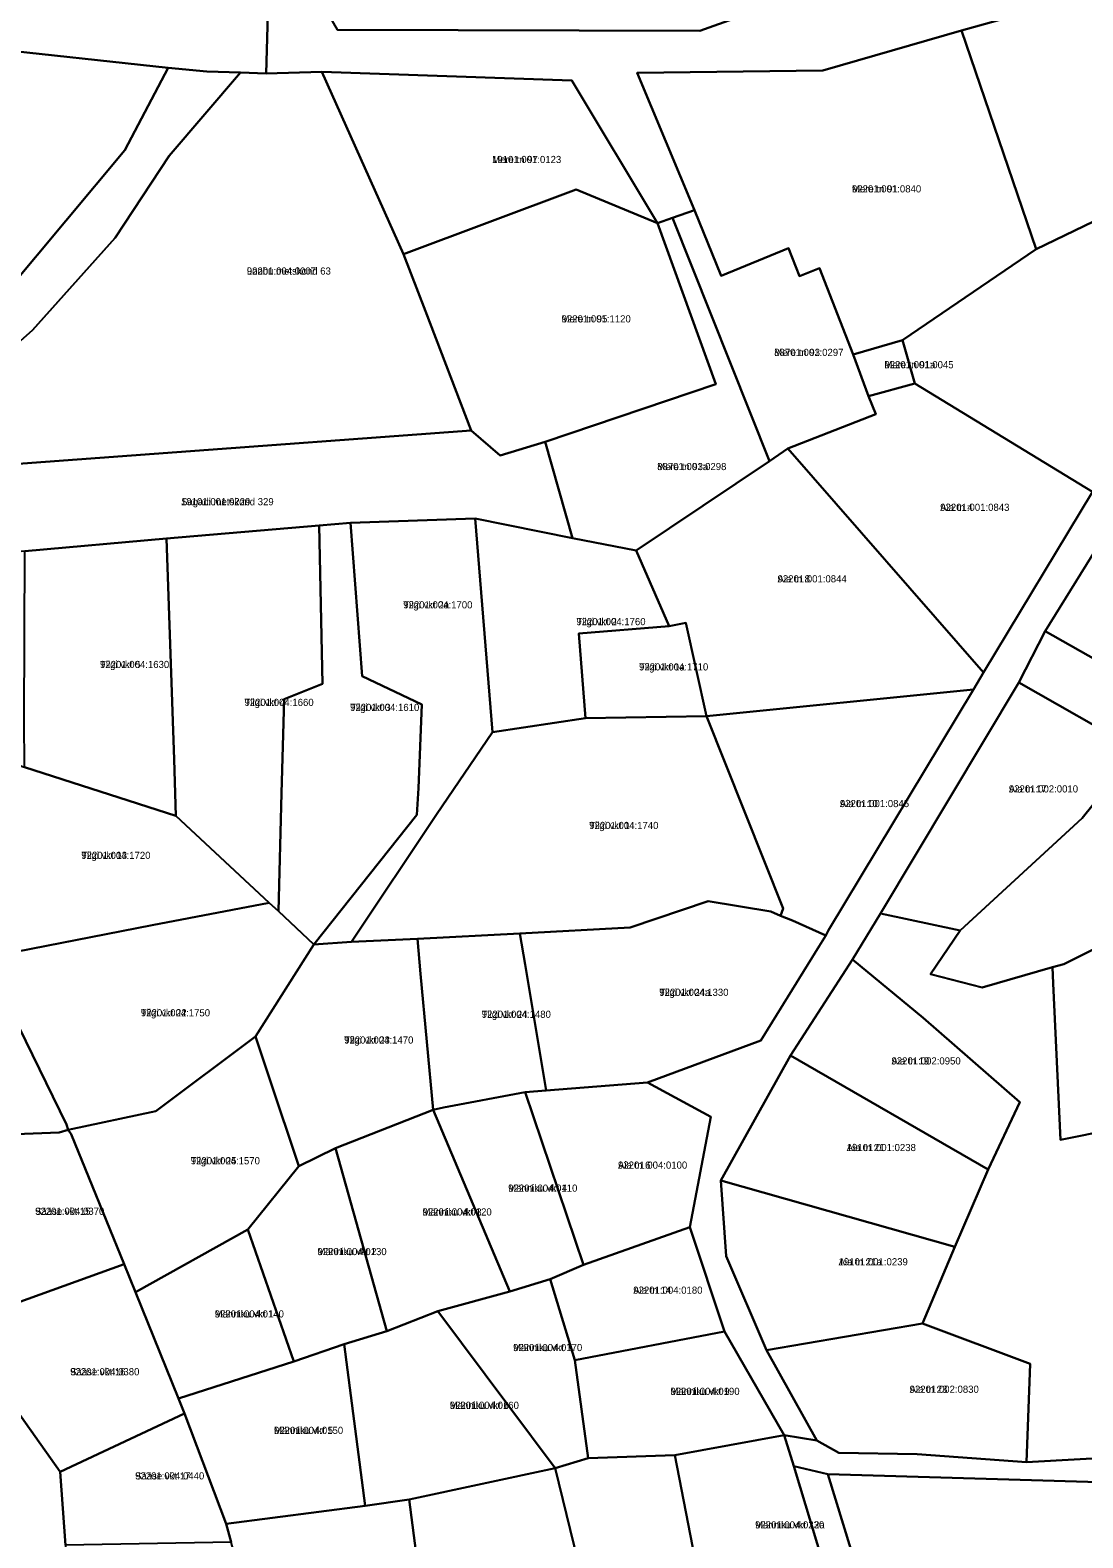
# Model space of a CAD drawing. Extents: x 601493 to 643081, y 6584980 to 6634019.
# Drawn here: x 610205.1 to 610425.7, y 6605427.7 to 6605743.8 of the extents above; entities that cross this region are included whole.
import ezdxf

# ---------------------------------------------------------------- set-up
doc = ezdxf.new("R2010")
doc.units = 0
for name, color, linetype in [('L_AADRESS', 7, 'Continuous'), ('PIIR', 7, 'Continuous'), ('TUNNUS', 7, 'Continuous')]:
    doc.layers.add(name, color=color, linetype=linetype)

msp = doc.modelspace()

# ---------------------------------------------------------------- linework, layer by layer
at = {"layer": 'PIIR'}
for points in [[(610289.98, 6605877.37), (610312.22, 6605837.37), (610292.43, 6605827.49), (610306.7, 6605795.06), (610329.91, 6605805.68), (610361.45, 6605749.4), (610345.37, 6605743.67), (610269.45, 6605743.86), (610216.52, 6605835.66)], [(610234, 6605735.88), (610224.92, 6605718.63), (610200.13, 6605689.04), (610179.93, 6605671.33), (610152.8, 6605650.08), (610007.23, 6605642.89), (609916.86, 6605639.32), (609908.54, 6605793.58), (609940.79, 6605777.71), (609965.38, 6605768.93), (609991.64, 6605761.28), (610037.32, 6605756.23), (610195.26, 6605740.09)], [(610400.23, 6605743.76), (610447.51, 6605756.94), (610456.9, 6605730.33), (610478.03, 6605737.44), (610478.38, 6605733.58), (610465.58, 6605711.74), (610456.1, 6605717.35), (610415.85, 6605697.91)], [(610370.48, 6605693.9), (610366.27, 6605692.21), (610364, 6605698.11), (610349.85, 6605692.34), (610344.31, 6605706.1), (610332.26, 6605734.83), (610371.17, 6605735.37), (610400.23, 6605743.76), (610415.85, 6605697.91), (610387.89, 6605678.79), (610377.56, 6605675.82)], [(610254.53, 6605734.73), (610266.17, 6605735.06), (610283.31, 6605696.84), (610287.89, 6605684.93), (610297.5, 6605659.86), (610164.51, 6605650.07), (610189.72, 6605666.95), (610205.55, 6605680.91), (610222.84, 6605700.29), (610234.19, 6605717.47), (610249.14, 6605734.93)], [(610266.17, 6605735.06), (610318.55, 6605733.23), (610336.54, 6605703.34), (610319.49, 6605710.43), (610283.31, 6605696.84)], [(610387.89, 6605678.79), (610415.85, 6605697.91), (610456.1, 6605717.35), (610465.58, 6605711.74), (610427.67, 6605647.04), (610390.42, 6605669.77)], [(610287.89, 6605684.93), (610283.31, 6605696.84), (610319.49, 6605710.43), (610336.54, 6605703.34), (610348.72, 6605669.59), (610312.97, 6605657.53), (610303.57, 6605654.66), (610297.5, 6605659.86)], [(610359.96, 6605653.45), (610339.7, 6605704.44), (610344.31, 6605706.1), (610349.85, 6605692.34), (610364, 6605698.11), (610366.27, 6605692.21), (610370.48, 6605693.9), (610377.56, 6605675.82), (610380.71, 6605667.07), (610382.27, 6605663.31), (610363.87, 6605656.09)], [(610348.72, 6605669.59), (610336.54, 6605703.34), (610339.7, 6605704.44), (610359.96, 6605653.45), (610332.06, 6605634.76), (610318.71, 6605637.3), (610312.97, 6605657.53)], [(610377.56, 6605675.82), (610387.89, 6605678.79), (610390.42, 6605669.77), (610380.71, 6605667.07)], [(610382.27, 6605663.31), (610380.71, 6605667.07), (610390.42, 6605669.77), (610427.67, 6605647.04), (610404.86, 6605609.15), (610363.87, 6605656.09)], [(610164.51, 6605650.07), (610297.5, 6605659.86), (610303.57, 6605654.66), (610312.97, 6605657.53), (610318.71, 6605637.3), (610298.29, 6605641.47), (610272.21, 6605640.5), (610265.64, 6605639.99), (610233.6, 6605637.22), (610203.92, 6605634.6), (610164.97, 6605631.15), (610135.51, 6605628.57)], [(610342.44, 6605619.56), (610339, 6605618.89), (610332.06, 6605634.76), (610359.96, 6605653.45), (610363.87, 6605656.09), (610404.86, 6605609.15), (610402.72, 6605605.58), (610346.79, 6605600)], [(610235.26, 6605590.9), (610233.6, 6605637.22), (610265.64, 6605639.99), (610266.32, 6605606.76), (610258.27, 6605603.57), (610257.74, 6605583.88), (610257.1, 6605559.12), (610255.11, 6605560.84), (610235.6, 6605579.07)], [(610257.1, 6605559.12), (610257.74, 6605583.88), (610258.27, 6605603.57), (610266.32, 6605606.76), (610265.64, 6605639.99), (610272.21, 6605640.5), (610274.6, 6605608.39), (610287.1, 6605602.44), (610286.44, 6605584.9), (610286.11, 6605579.31), (610264.52, 6605552.15)], [(610264.52, 6605552.15), (610286.11, 6605579.31), (610286.44, 6605584.9), (610287.1, 6605602.44), (610274.6, 6605608.39), (610272.21, 6605640.5), (610298.29, 6605641.47), (610301.95, 6605596.67), (610290.24, 6605579.37), (610272.36, 6605552.68)], [(610298.29, 6605641.47), (610318.71, 6605637.3), (610332.06, 6605634.76), (610339, 6605618.89), (610320.04, 6605617.33), (610321.45, 6605599.6), (610301.95, 6605596.67)], [(610431.69, 6605640.26), (610459.02, 6605620.13), (610444.82, 6605602.51), (610417.77, 6605617.8)], [(610203.77, 6605599.26), (610203.92, 6605634.6), (610233.6, 6605637.22), (610235.26, 6605590.9), (610235.6, 6605579.07), (610203.83, 6605589.28)], [(610425.55, 6605578.59), (610437.08, 6605592.92), (610444.82, 6605602.51), (610459.02, 6605620.13), (610481.55, 6605603.61), (610493.38, 6605601), (610476.79, 6605587.15), (610473.64, 6605584.61), (610451.8, 6605565.68), (610448.69, 6605563.75), (610435.15, 6605554.82), (610421.65, 6605548.04), (610419.3, 6605547.36), (610404.58, 6605543.12), (610393.75, 6605545.93), (610399.96, 6605555.08)], [(610339, 6605618.89), (610342.44, 6605619.56), (610346.79, 6605600), (610321.45, 6605599.6), (610320.04, 6605617.33)], [(610417.77, 6605617.8), (610444.82, 6605602.51), (610437.08, 6605592.92), (610412.26, 6605607.05)], [(610371.77, 6605554.01), (610364.84, 6605557.17), (610362.3, 6605558.15), (610362.89, 6605559.68), (610346.79, 6605600), (610402.72, 6605605.58), (610372.38, 6605555.13)], [(610412.26, 6605607.05), (610437.08, 6605592.92), (610425.55, 6605578.59), (610399.96, 6605555.08), (610383.24, 6605558.65)], [(610286.21, 6605553.31), (610272.36, 6605552.68), (610290.24, 6605579.37), (610301.95, 6605596.67), (610321.45, 6605599.6), (610346.79, 6605600), (610362.89, 6605559.68), (610362.3, 6605558.15), (610360.27, 6605559.08), (610347.11, 6605561.19), (610330.81, 6605555.72), (610307.67, 6605554.47)], [(610193.42, 6605553.76), (610179.24, 6605586.31), (610185.05, 6605587.59), (610199.44, 6605590.81), (610203.83, 6605589.28), (610235.6, 6605579.07), (610255.11, 6605560.84), (610230.64, 6605556.2), (610195.54, 6605549.33)], [(610419.45, 6605543.94), (610419.3, 6605547.36), (610421.65, 6605548.04), (610435.15, 6605554.82), (610448.69, 6605563.75), (610474.41, 6605536.59), (610486.26, 6605524.34), (610420.96, 6605511.15)], [(610212.7, 6605514.42), (610195.54, 6605549.33), (610230.64, 6605556.2), (610255.11, 6605560.84), (610257.1, 6605559.12), (610264.52, 6605552.15), (610252.24, 6605532.84), (610231.4, 6605517.17), (610213.02, 6605513.29)], [(610313.16, 6605521.52), (610308.76, 6605547.92), (610307.67, 6605554.47), (610330.81, 6605555.72), (610347.11, 6605561.19), (610360.27, 6605559.08), (610362.3, 6605558.15), (610364.84, 6605557.17), (610371.77, 6605554.01), (610370.4, 6605551.79), (610358.19, 6605532.03), (610334.42, 6605523.22)], [(610414.59, 6605464.21), (610392.09, 6605472.66), (610398.82, 6605488.75), (610405.83, 6605504.94), (610412.44, 6605519.07), (610392.2, 6605536.79), (610377.39, 6605549.01), (610383.24, 6605558.65), (610399.96, 6605555.08), (610393.75, 6605545.93), (610404.58, 6605543.12), (610419.3, 6605547.36), (610419.45, 6605543.94), (610420.96, 6605511.15), (610486.26, 6605524.34), (610516.24, 6605530.61), (610444.31, 6605490.25), (610482.23, 6605448.56), (610436.34, 6605444.88), (610413.82, 6605443.63)], [(610168.93, 6605513.42), (610165.39, 6605550.35), (610193.42, 6605553.76), (610195.54, 6605549.33), (610212.7, 6605514.42), (610213.02, 6605513.29), (610211.12, 6605512.73), (610187.45, 6605511.78), (610169.17, 6605510.83)], [(610289.48, 6605517.5), (610286.88, 6605546), (610286.21, 6605553.31), (610307.67, 6605554.47), (610308.76, 6605547.92), (610313.16, 6605521.52), (610308.82, 6605521.17), (610291.69, 6605517.98)], [(610261.33, 6605505.69), (610255.18, 6605524.03), (610252.24, 6605532.84), (610264.52, 6605552.15), (610272.36, 6605552.68), (610286.21, 6605553.31), (610286.88, 6605546), (610289.48, 6605517.5), (610269.01, 6605509.42)], [(610377.39, 6605549.01), (610392.2, 6605536.79), (610412.44, 6605519.07), (610405.83, 6605504.94), (610364.41, 6605528.88)], [(610224.73, 6605485.11), (610213.63, 6605512.35), (610213.02, 6605513.29), (610231.4, 6605517.17), (610252.24, 6605532.84), (610255.18, 6605524.03), (610261.33, 6605505.69), (610250.7, 6605492.36), (610227.16, 6605479.27)], [(610349.77, 6605502.66), (610364.41, 6605528.88), (610405.83, 6605504.94), (610398.82, 6605488.75)], [(610308.82, 6605521.17), (610313.16, 6605521.52), (610334.42, 6605523.22), (610347.68, 6605515.97), (610343.27, 6605492.86), (610320.99, 6605484.99)], [(610289.48, 6605517.5), (610291.69, 6605517.98), (610308.82, 6605521.17), (610320.99, 6605484.99), (610314.03, 6605481.95), (610305.55, 6605479.38)], [(610269.01, 6605509.42), (610289.48, 6605517.5), (610305.55, 6605479.38), (610290.48, 6605475.26), (610279.81, 6605471.08)], [(610187.59, 6605508.29), (610187.45, 6605511.78), (610211.12, 6605512.73), (610213.02, 6605513.29), (610213.63, 6605512.35), (610224.73, 6605485.11), (610189.49, 6605472.42)], [(610250.7, 6605492.36), (610261.33, 6605505.69), (610269.01, 6605509.42), (610279.81, 6605471.08), (610270.87, 6605468.37), (610260.3, 6605464.72)], [(610350.93, 6605486.8), (610349.77, 6605502.66), (610398.82, 6605488.75), (610392.09, 6605472.66), (610359.37, 6605467.07)], [(610227.16, 6605479.27), (610250.7, 6605492.36), (610260.3, 6605464.72), (610236.17, 6605456.97)], [(610314.03, 6605481.95), (610320.99, 6605484.99), (610343.27, 6605492.86), (610350.59, 6605470.98), (610319.23, 6605464.98)], [(610189.49, 6605472.42), (610224.73, 6605485.11), (610227.16, 6605479.27), (610236.17, 6605456.97), (610237.38, 6605453.78), (610211.34, 6605441.61)], [(610290.48, 6605475.26), (610305.55, 6605479.38), (610314.03, 6605481.95), (610319.23, 6605464.98), (610322.02, 6605444.43), (610315.09, 6605442.37)], [(610365.08, 6605442.74), (610363.1, 6605449.26), (610369.91, 6605448.17), (610374.55, 6605445.54), (610390.95, 6605445.31), (610413.82, 6605443.63), (610436.34, 6605444.88), (610482.23, 6605448.56), (610533.67, 6605470.67), (610528.78, 6605478.36), (610536.85, 6605483.54), (610544.4, 6605469.62), (610575.81, 6605483.42), (610580.7, 6605474.82), (610547.79, 6605453.01), (610539.84, 6605466.91), (610525.13, 6605461.9), (610480.16, 6605442.56), (610436.24, 6605439.2), (610372.2, 6605441.12)], [(610275.25, 6605434.48), (610270.87, 6605468.37), (610279.81, 6605471.08), (610290.48, 6605475.26), (610315.09, 6605442.37), (610284.46, 6605435.81)], [(610187.99, 6605386.66), (610186.4, 6605430.65), (610187.86, 6605448.11), (610189.49, 6605472.42), (610211.34, 6605441.61), (610212.45, 6605426.19), (610215.53, 6605388.7), (610215.74, 6605386.18), (610188.09, 6605384.17)], [(610369.91, 6605448.17), (610359.37, 6605467.07), (610392.09, 6605472.66), (610414.59, 6605464.21), (610413.82, 6605443.63), (610390.95, 6605445.31), (610374.55, 6605445.54)], [(610237.38, 6605453.78), (610236.17, 6605456.97), (610260.3, 6605464.72), (610270.87, 6605468.37), (610275.25, 6605434.48), (610246.16, 6605430.68)], [(610319.23, 6605464.98), (610350.59, 6605470.98), (610363.1, 6605449.26), (610340.17, 6605445.11), (610322.02, 6605444.43)], [(610237.38, 6605453.78), (610246.16, 6605430.68), (610247.21, 6605426.87), (610212.45, 6605426.19), (610211.34, 6605441.61)], [(610346.68, 6605411.6), (610340.17, 6605445.11), (610363.1, 6605449.26), (610365.08, 6605442.74), (610373.77, 6605414.08), (610347.08, 6605409.64)], [(610323.8, 6605406.65), (610315.09, 6605442.37), (610322.02, 6605444.43), (610340.17, 6605445.11), (610346.68, 6605411.6), (610347.08, 6605409.64), (610324.35, 6605404.77)], [(610289.57, 6605396.43), (610284.46, 6605435.81), (610315.09, 6605442.37), (610323.8, 6605406.65), (610324.35, 6605404.77), (610289.92, 6605394.24)], [(610416.39, 6605307.74), (610415.41, 6605310.5), (610414.05, 6605314.35), (610410.84, 6605323.43), (610398.59, 6605359.7), (610383.2, 6605405.34), (610372.2, 6605441.12), (610436.24, 6605439.2), (610480.16, 6605442.56), (610552.14, 6605261.1), (610499.49, 6605267.13), (610495.66, 6605267.57), (610500.46, 6605245.8), (610496.03, 6605246.32), (610438.06, 6605252.8)], [(610257.7, 6605388.42), (610256.95, 6605391.19), (610247.21, 6605426.87), (610246.16, 6605430.68), (610275.25, 6605434.48), (610284.46, 6605435.81), (610289.57, 6605396.43), (610289.92, 6605394.24), (610269.21, 6605389.18)]]:
    msp.add_lwpolyline(points, close=True, dxfattribs=at)
for points in [[(609994.6, 6605776.04), (610064.24, 6605768.14), (610178.33, 6605756.82), (610206.94, 6605753.24), (610233.04, 6605752.07), (610254.91, 6605749.59), (610254.53, 6605734.73), (610249.14, 6605734.93), (610242.11, 6605735.12), (610234, 6605735.88), (610195.26, 6605740.09), (610037.32, 6605756.23), (609991.64, 6605761.28)], [(610447.51, 6605756.94), (610400.23, 6605743.76), (610371.17, 6605735.37), (610332.26, 6605734.83), (610344.31, 6605706.1), (610339.7, 6605704.44), (610336.54, 6605703.34), (610318.55, 6605733.23), (610266.17, 6605735.06), (610254.53, 6605734.73), (610254.91, 6605749.59)], [(610269.45, 6605743.86), (610345.37, 6605743.67), (610361.45, 6605749.4)], [(610200.13, 6605689.04), (610224.92, 6605718.63), (610234, 6605735.88), (610242.11, 6605735.12), (610249.14, 6605734.93), (610234.19, 6605717.47), (610222.84, 6605700.29), (610205.55, 6605680.91), (610189.72, 6605666.95)], [(610431.69, 6605640.26), (610417.77, 6605617.8), (610412.26, 6605607.05), (610383.24, 6605558.65), (610377.39, 6605549.01), (610364.41, 6605528.88), (610349.77, 6605502.66), (610350.93, 6605486.8), (610359.37, 6605467.07), (610369.91, 6605448.17), (610363.1, 6605449.26), (610350.59, 6605470.98), (610343.27, 6605492.86), (610347.68, 6605515.97), (610334.42, 6605523.22), (610358.19, 6605532.03), (610370.4, 6605551.79), (610371.77, 6605554.01), (610372.38, 6605555.13), (610402.72, 6605605.58), (610404.86, 6605609.15), (610427.67, 6605647.04)], [(610373.77, 6605414.08), (610365.08, 6605442.74), (610372.2, 6605441.12), (610383.2, 6605405.34)]]:
    msp.add_lwpolyline(points, dxfattribs=at)

# ---------------------------------------------------------------- texts
at = {"layer": 'L_AADRESS'}
for s, p in [('Mere tn 97', (610301.85, 6605715.95)), ('Mere tn 91', (610377.28, 6605709.79)), ('Loobu metskond 63', (610250.45, 6605692.57)), ('Mere tn 95', (610316.42, 6605682.54)), ('Mere tn 93', (610360.99, 6605675.51)), ('Mere tn 91a', (610384.07, 6605672.93)), ('Mere tn 93a', (610336.46, 6605651.58)), ('Sagadi metskond 329', (610236.68, 6605644.21)), ('Aia tn 4', (610395.77, 6605643.03)), ('Aia tn 8', (610361.68, 6605628.04)), ('Tiigi vkt 2a', (610283.24, 6605622.59)), ('Tiigi vkt 2', (610319.52, 6605619.07)), ('Tiigi vkt 5', (610219.69, 6605610.09)), ('Tiigi vkt 1a', (610332.66, 6605609.58)), ('Tiigi vkt 4', (610249.96, 6605602.14)), ('Tiigi vkt 3', (610272.1, 6605601.09)), ('Aia tn 17', (610410.16, 6605584)), ('Aia tn 10', (610374.75, 6605580.93)), ('Tiigi vkt 1', (610322.22, 6605576.34)), ('Tiigi vkt 13', (610215.77, 6605570.07)), ('Tiigi vkt 24a', (610336.9, 6605541.36)), ('Tiigi vkt 22', (610228.25, 6605537.07)), ('Tiigi vkt 24', (610299.68, 6605536.75)), ('Tiigi vkt 23', (610270.86, 6605531.36)), ('Aia tn 19', (610385.56, 6605526.98)), ('Aia tn 21', (610376.17, 6605508.82)), ('Tiigi vkt 25', (610238.7, 6605506.05)), ('Aia tn 6', (610328.25, 6605505.14)), ('Männiku vkt 4', (610305.23, 6605500.31)), ('Sääse vkt 15', (610206.09, 6605495.46)), ('Männiku vkt 3', (610287.28, 6605495.32)), ('Männiku vkt 2', (610265.26, 6605487.01)), ('Aia tn 21a', (610374.48, 6605484.87)), ('Aia tn 14', (610331.45, 6605478.92)), ('Männiku vkt 1', (610243.73, 6605473.94)), ('Männiku vkt 7', (610306.25, 6605466.89)), ('Sääse vkt 16', (610213.44, 6605461.82)), ('Männiku vkt 9', (610339.23, 6605457.71)), ('Aia tn 23', (610389.36, 6605458.15)), ('Männiku vkt 6', (610292.98, 6605454.78)), ('Männiku vkt 5', (610256.15, 6605449.53)), ('Sääse vkt 17', (610227.04, 6605439.99)), ('Männiku vkt 12a', (610356.97, 6605429.72))]:
    msp.add_text(s, height=1.5, dxfattribs=at).set_placement(p)
at = {"layer": 'TUNNUS'}
for s, p in [('19101:001:0123', (610301.85, 6605715.95)), ('92201:001:0840', (610377.28, 6605709.79)), ('92201:004:0007', (610250.45, 6605692.57)), ('92201:001:1120', (610316.42, 6605682.54)), ('88701:001:0297', (610360.99, 6605675.51)), ('92201:001:0045', (610384.07, 6605672.93)), ('88701:001:0298', (610336.46, 6605651.58)), ('19101:001:0229', (610236.68, 6605644.21)), ('92201:001:0843', (610395.77, 6605643.03)), ('92201:001:0844', (610361.68, 6605628.04)), ('92201:004:1700', (610283.24, 6605622.59)), ('92201:004:1760', (610319.52, 6605619.07)), ('92201:004:1630', (610219.69, 6605610.09)), ('92201:004:1710', (610332.66, 6605609.58)), ('92201:004:1660', (610249.96, 6605602.14)), ('92201:004:1610', (610272.1, 6605601.09)), ('92201:002:0010', (610410.16, 6605584)), ('92201:001:0845', (610374.75, 6605580.93)), ('92201:004:1740', (610322.22, 6605576.34)), ('92201:004:1720', (610215.77, 6605570.07)), ('92201:004:1330', (610336.9, 6605541.36)), ('92201:004:1750', (610228.25, 6605537.07)), ('92201:004:1480', (610299.68, 6605536.75)), ('92201:004:1470', (610270.86, 6605531.36)), ('92201:002:0950', (610385.56, 6605526.98)), ('19101:001:0238', (610376.17, 6605508.82)), ('92201:004:1570', (610238.7, 6605506.05)), ('92201:004:0100', (610328.25, 6605505.14)), ('92201:004:0110', (610305.23, 6605500.31)), ('92201:004:0370', (610206.09, 6605495.46)), ('92201:004:0120', (610287.28, 6605495.32)), ('92201:004:0130', (610265.26, 6605487.01)), ('19101:001:0239', (610374.48, 6605484.87)), ('92201:004:0180', (610331.45, 6605478.92)), ('92201:004:0140', (610243.73, 6605473.94)), ('92201:004:0170', (610306.25, 6605466.89)), ('92201:004:0380', (610213.44, 6605461.82)), ('92201:004:0190', (610339.23, 6605457.71)), ('92201:002:0830', (610389.36, 6605458.15)), ('92201:004:0160', (610292.98, 6605454.78)), ('92201:004:0150', (610256.15, 6605449.53)), ('92201:004:0440', (610227.04, 6605439.99)), ('92201:004:0230', (610356.97, 6605429.72))]:
    msp.add_text(s, height=1.5, dxfattribs=at).set_placement(p)

doc.saveas('drawing.dxf')
